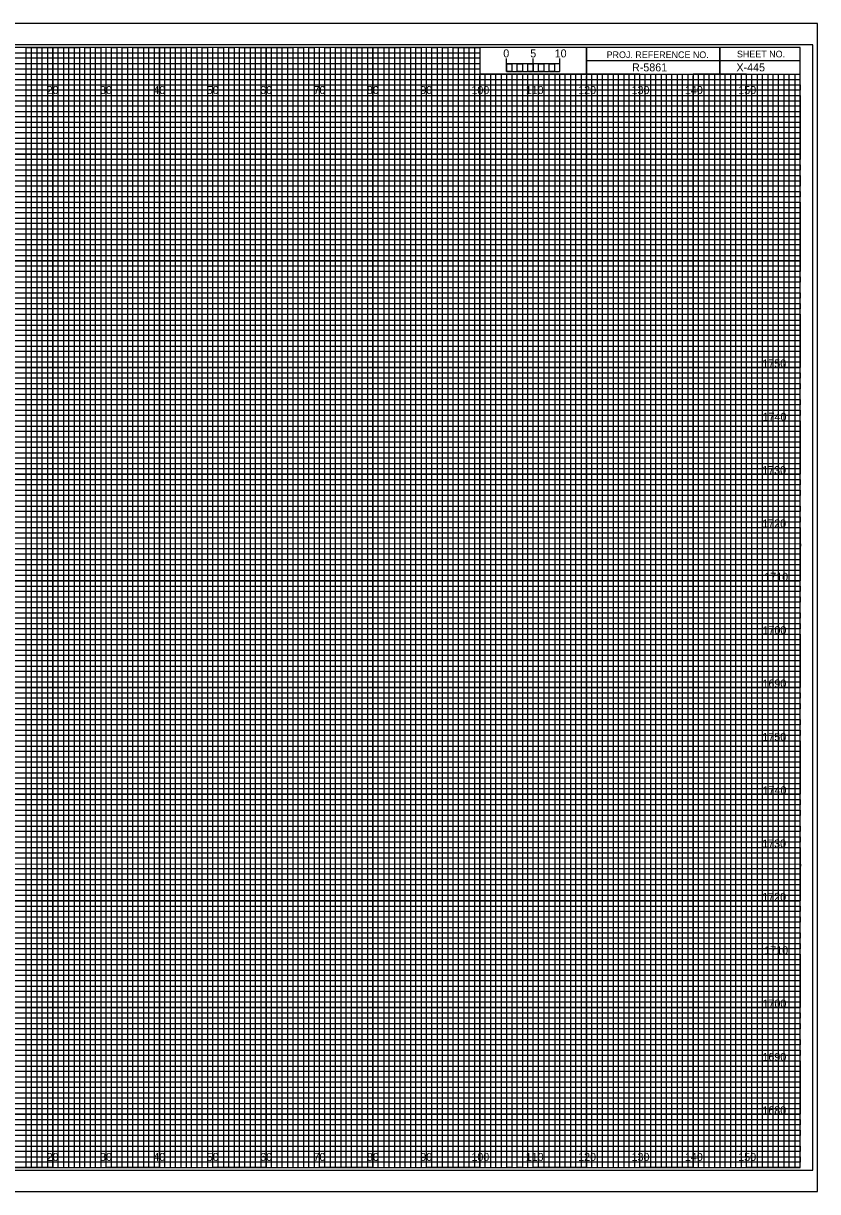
# Model space of a CAD drawing. Extents: x -13 to 323, y -5 to 1314.
# Drawn here: x 174.5 to 323.3, y 875.5 to 1094.5 of the extents above; entities that cross this region are included whole.
import ezdxf

# ---------------------------------------------------------------- set-up
doc = ezdxf.new("R2010")
doc.units = 0
for name, color, linetype in [('Prop XS Bar Scale Labels', 7, 'Continuous'), ('Prop XS Project Number', 7, 'Continuous'), ('Prop XS Sheet Number', 7, 'Continuous'), ('Raster_Level_0', 7, 'Continuous'), ('Scratch_Level_3', 7, 'Continuous'), ('Sheet Cross Section CELL', 7, 'Continuous'), ('Sheet Cross Section Grid Major CELL', 7, 'Continuous'), ('Sheet Cross Section Grid Middle CELL', 7, 'Continuous'), ('Sheet Cross Section Grid Minor 1 CELL', 7, 'Continuous'), ('Sheet Cross Section Grid Minor 2 CELL', 7, 'Continuous'), ('Sheet Cross Section Scale CELL', 7, 'Continuous'), ('Sheet Cutting Line CELL', 7, 'Continuous'), ('Sheet DOT Grid CELL', 7, 'Continuous'), ('Sheet Plot Border Inside CELL', 7, 'Continuous'), ('Sheet Plot Border Outside CELL', 7, 'Continuous')]:
    doc.layers.add(name, color=color, linetype=linetype)

msp = doc.modelspace()

# ---------------------------------------------------------------- linework, layer by layer
at = {"layer": 'Sheet Cross Section CELL'}
for p, q in [((305, 1090), (305, 1085)), ((305, 1085), (305, 1090)), ((280, 1087.5), (280, 1085)), ((320, 1087.49), (280, 1087.49)), ((280, 1085), (320, 1085))]:
    msp.add_line(p, q, dxfattribs=at)
for points in [[(320, 1090), (0, 1090), (0, 880), (320, 880)], [(280, 1090), (260, 1090), (260, 1085.03), (280, 1085.03)], [(320, 1090), (280, 1090), (280, 1085), (320, 1085)]]:
    msp.add_lwpolyline(points, close=True, dxfattribs=at)
at = {"layer": 'Sheet Cross Section Grid Major CELL'}
for p, q in [((190, 1090), (180, 1090)), ((180, 1090), (180, 880)), ((190, 880), (190, 1090)), ((210, 1090), (200, 1090)), ((200, 1090), (200, 880)), ((210, 880), (210, 1090)), ((230, 1090), (220, 1090)), ((220, 1090), (220, 880)), ((230, 880), (230, 1090)), ((250, 1090), (240, 1090)), ((240, 1090), (240, 880)), ((250, 880), (250, 1090)), ((260, 1090), (260, 880)), ((270, 880), (270, 1085)), ((290, 1085), (280, 1085)), ((280, 1085), (280, 880)), ((290, 880), (290, 1085)), ((310, 1085), (300, 1085)), ((300, 1085), (300, 880)), ((310, 880), (310, 1085)), ((180, 880), (170, 880)), ((200, 880), (190, 880)), ((220, 880), (210, 880)), ((240, 880), (230, 880)), ((260, 880), (250, 880)), ((280, 880), (270, 880)), ((300, 880), (290, 880)), ((320, 880), (310, 880)), ((320, 880), (320, 880))]:
    msp.add_line(p, q, dxfattribs=at)
for points in [[(0, 1080), (320, 1080), (320, 1070), (0, 1070)], [(0, 1060), (320, 1060), (320, 1050), (0, 1050)], [(0, 1040), (320, 1040), (320, 1030), (0, 1030)], [(0, 1020), (320, 1020), (320, 1010), (0, 1010)], [(0, 1000), (320, 1000), (320, 990), (0, 990)], [(0, 980), (320, 980), (320, 970), (0, 970)], [(0, 960), (320, 960), (320, 950), (0, 950)], [(0, 940), (320, 940), (320, 930), (0, 930)], [(0, 920), (320, 920), (320, 910), (0, 910)], [(0, 900), (320, 900), (320, 890), (0, 890)]]:
    msp.add_lwpolyline(points, dxfattribs=at)
at = {"layer": 'Sheet Cross Section Grid Middle CELL'}
for points in [[(165, 880), (175, 880), (175, 1090), (185, 1090), (185, 880), (195, 880), (195, 1090), (205, 1090), (205, 880), (215, 880), (215, 1090), (225, 1090), (225, 880), (235, 880), (235, 1090), (245, 1090), (245, 880), (255, 880), (255, 1090), (259.93, 1090), (260, 1090), (260, 1085), (264.99, 1085), (264.99, 880), (275, 880), (275, 1085), (285, 1085), (285, 880), (295, 880), (295, 1085), (305, 1085), (305, 880), (315, 880), (315, 1085)], [(0, 1085), (275, 1085)], [(0, 1065), (320, 1065), (320, 1075), (0, 1075)], [(0, 1045), (320, 1045), (320, 1055), (0, 1055)], [(0, 1025), (320, 1025), (320, 1035), (0, 1035)], [(0, 1005), (320, 1005), (320, 1015), (0, 1015)], [(0, 985), (320, 985), (320, 995), (0, 995)], [(0, 965), (320, 965), (320, 975), (0, 975)], [(0, 945), (320, 945), (320, 955), (0, 955)], [(0, 925), (320, 925), (320, 935), (0, 935)], [(0, 905), (320, 905), (320, 915), (0, 915)], [(0, 885), (320, 885), (320, 895), (0, 895)]]:
    msp.add_lwpolyline(points, dxfattribs=at)
at = {"layer": 'Sheet Cross Section Grid Minor 1 CELL'}
for p, q in [((0, 1089), (260, 1089)), ((260, 1089), (260, 1087.98)), ((260, 1087.98), (0, 1087.98)), ((0, 1087), (260, 1087)), ((260, 1087), (260, 1085.89)), ((260, 1085.89), (0, 1085.89)), ((0, 1084), (320, 1084))]:
    msp.add_line(p, q, dxfattribs=at)
for points in [[(0, 1083), (270, 1083), (320, 1083), (320, 1082), (0, 1082)], [(0, 1081), (320, 1081), (320, 1079), (0, 1079)], [(0, 1078), (320, 1078), (320, 1077), (0, 1076.98)], [(0, 1076), (320, 1076), (320, 1074), (0, 1074)], [(0, 1073), (320, 1073), (320, 1072), (0, 1072)], [(0, 1071), (320, 1071), (320, 1069), (0, 1069)], [(0, 1068), (320, 1068), (320, 1067), (0, 1067)], [(0, 1066), (320, 1066), (320, 1064), (0, 1064)], [(0, 1063), (320, 1063), (320, 1062), (0, 1062)], [(0, 1061), (320, 1061), (320, 1059), (0, 1059)], [(0, 1058), (320, 1058), (320, 1057), (0, 1057)], [(0, 1056), (320, 1056), (320, 1053.95), (320, 1053), (320, 1052), (0, 1052)], [(0, 1054), (320, 1054), (320, 1053), (0, 1053)], [(0, 1051), (320, 1051), (320, 1049), (0, 1049.03)], [(0, 1049.03), (320, 1049), (320, 1048), (0, 1048)], [(0, 1047), (320, 1047), (320, 1046), (0, 1046)], [(0, 1044), (320, 1044), (320, 1043), (0, 1043)], [(0, 1042), (320, 1042), (320, 1041), (0, 1041)], [(-0.07, 1038.89), (320, 1038.89), (320, 1037.88), (-0.07, 1037.88)], [(0, 1037), (320, 1037), (320, 1036), (0, 1036)], [(0, 1034), (320, 1034), (320, 1033), (0, 1033)], [(0, 1032), (320, 1032), (320, 1031), (0, 1031)], [(0, 1029), (320, 1029), (320, 1028), (0, 1028)], [(0, 1027), (320, 1027), (320, 1026), (0, 1026)], [(0, 1024), (320, 1024), (320, 1023), (0, 1023)], [(0, 1022), (320, 1022), (320, 1021), (0, 1021)], [(0, 1019), (320, 1019), (319.99, 1017.98), (0, 1018)], [(0, 1017), (320, 1017), (320, 1016), (0, 1016)], [(0, 1014), (320, 1014), (320, 1013), (0, 1013)], [(0, 1012), (320, 1012), (320, 1011), (0, 1011)], [(0, 1009), (320, 1009), (320, 1008), (0, 1008)], [(0, 1007), (320, 1007), (320, 1006), (0, 1006)], [(0, 1004), (320, 1004), (320, 1003), (0, 1003)], [(0, 1002), (320, 1002), (320, 1001), (0, 1001)], [(0, 999), (320, 999), (320, 998), (0, 998)], [(0, 996.99), (320.07, 996.91), (320, 996), (0, 996)], [(0, 994), (320, 994), (320, 993), (0, 993)], [(0, 992), (320, 992), (320, 991), (0, 991)], [(0, 989), (320, 989), (320, 988), (0, 988)], [(0, 987), (320, 987), (320, 986), (0, 986)], [(0, 984), (320, 984), (320, 983), (0, 983)], [(0, 982), (320, 982), (320, 981), (0, 981)], [(0, 979), (320, 979), (320, 978), (0, 978)], [(0, 977), (320, 977), (320, 976), (0, 976)], [(0, 974), (320, 974), (320, 973), (0, 973)], [(0, 972), (320, 972), (320, 971), (0, 971)], [(0, 969), (320, 969), (320, 968), (0, 968)], [(0, 967), (320, 967), (320, 966), (0, 966)], [(0, 964), (320, 964), (320, 963), (0, 963)], [(0, 962), (320, 962), (320, 961), (0, 961)], [(0, 959), (320, 959), (319.99, 957.98), (0, 958)], [(0, 957), (320, 957), (320, 956), (0, 956)], [(0, 954), (320, 954), (320, 953), (0, 953)], [(0, 952), (320, 952), (320, 951), (0, 951)], [(0, 949), (320, 949), (320, 948), (0, 948)], [(0, 947), (320, 947), (320, 946), (0, 946)], [(0, 944), (320, 944), (320, 943), (0, 943)], [(0, 942), (320, 942), (320, 941), (0, 941)], [(0, 939), (320, 939), (320, 938), (0, 938)], [(0, 936.99), (320.07, 936.91), (320, 936), (0, 936)], [(0, 934), (320, 934), (320, 933), (0, 933)], [(0, 932), (320, 932), (320, 931), (0, 931)], [(0, 929), (320, 929), (320, 928), (0, 928)], [(0, 927), (320, 927), (320, 926), (0, 926)], [(0, 924), (320, 924), (320, 923), (0, 923)], [(0, 922), (320, 922), (320, 921), (0, 921)], [(0, 919), (320, 919), (320, 918), (0, 918)], [(0, 917), (320, 917), (320, 916), (0, 916)], [(0, 914), (320, 914), (320, 913), (0, 913)], [(0, 912), (320, 912), (320, 911), (0, 911)], [(0, 909), (320, 909), (320, 908), (0, 908)], [(0, 907), (320, 907), (320, 906), (0, 906)], [(0, 904), (320, 904), (320, 903), (0, 903)], [(0, 902), (320, 902), (320, 901), (0, 901)], [(0, 899), (320, 899), (320, 898), (0, 898)], [(0, 897), (320, 897), (320, 896), (0, 896)], [(0, 894), (320, 894), (320, 893), (0, 893)], [(0, 892), (320, 892), (320, 891), (0, 891)], [(0, 889), (320, 889), (320, 888), (0, 888)], [(0, 887), (320, 887), (320, 886), (0, 886)], [(0, 884), (320, 884), (320, 883), (0, 883)], [(0, 882), (320, 882), (320, 881), (0, 881)]]:
    msp.add_lwpolyline(points, dxfattribs=at)
at = {"layer": 'Sheet Cross Section Grid Minor 2 CELL'}
for p, q in [((267, 1085), (266.01, 1085)), ((266.01, 1085), (266.01, 880)), ((267, 880), (267, 1085)), ((269, 1085), (268, 1085)), ((268, 1085), (268, 880)), ((269, 880), (269, 1085)), ((266.01, 880), (265, 880)), ((268, 880), (267, 880))]:
    msp.add_line(p, q, dxfattribs=at)
for points in [[(175, 880), (176, 880), (176, 1090), (177, 1090), (177, 880)], [(177, 880), (178, 880), (178, 1090), (179, 1090), (179, 880)], [(180, 880), (181, 880), (181, 1090), (182, 1090), (182, 880)], [(182, 880), (183, 880), (183, 1090), (184, 1090), (184, 880)], [(185, 880), (186, 880), (186, 1090), (187, 1090), (187, 880)], [(187, 880), (188, 880), (188, 1090), (189, 1090), (189, 880)], [(190, 880), (191, 880), (191, 1090), (192, 1090), (192, 880)], [(192, 880), (193, 880), (193, 1090), (194, 1090), (194, 880)], [(195, 880), (196, 880), (196, 1090), (197, 1090), (197, 880)], [(197, 880), (198, 880), (198, 1090), (199, 1090), (199, 880)], [(200, 880), (201, 880), (201, 1090), (202, 1090), (202, 880)], [(202, 880), (203, 880), (203, 1090), (204, 1090), (204, 880)], [(205, 880), (206, 880), (206, 1090), (207, 1090), (207, 880)], [(207, 880), (208, 880), (208, 1090), (209, 1090), (209, 880)], [(210, 880), (211, 880), (211, 1090), (212, 1090), (212, 880)], [(212, 880), (213, 880), (213, 1090), (214, 1090), (214, 880)], [(215, 880), (216, 880), (216, 1090), (217, 1090), (217, 880)], [(217, 880), (218, 880), (218, 1090), (219, 1090), (219, 880)], [(220, 880), (221, 880), (221, 1090), (222, 1090), (222, 880)], [(222, 880), (223, 880), (223, 1090), (224, 1090), (224, 880)], [(225, 880), (226, 880), (226, 1090), (227, 1090), (227, 880)], [(227, 880), (228, 880), (228, 1090), (229, 1090), (229, 880)], [(230, 880), (231, 880), (231, 1090), (232, 1090), (232, 880)], [(232, 880), (233, 880), (233, 1090), (234, 1090), (234, 880)], [(235, 880), (236, 880), (236, 1090), (237, 1090), (237, 880)], [(237, 880), (238, 880), (238, 1090), (239, 1090), (239, 880)], [(240, 880), (241, 880), (241, 1090), (242, 1090), (242, 880)], [(242, 880), (243, 880), (243, 1090), (244, 1090), (244, 880)], [(245, 880), (246, 880), (246, 1090), (247, 1090), (247, 880)], [(247, 880), (248, 880), (248, 1090), (249, 1090), (249, 880)], [(250, 880), (251, 880), (251, 1090), (252, 1090), (252, 880)], [(252, 880), (253, 880), (253, 1090), (254, 1090), (254, 880)], [(255, 880), (256, 880), (256, 1090), (257, 1090), (257, 880)], [(257, 880), (258, 880), (258, 1090), (259, 1090), (259, 880)], [(260, 880), (261, 880), (261, 1085), (262.02, 1085), (262.02, 880)], [(262, 880), (263, 880), (263, 1085), (263.99, 1085), (263.99, 880)], [(270, 880), (270.98, 880), (270.98, 1085), (272, 1085), (272, 880)], [(272, 880), (273, 880), (273, 1085), (274.05, 1085), (274.05, 880)], [(275, 880), (276, 880), (276, 1085), (277, 1085), (277, 880)], [(277, 880), (278, 880), (278, 1085), (279, 1085), (279, 880)], [(280, 880), (281, 880), (281, 1085), (282, 1085), (282, 880)], [(282, 880), (283, 880), (283, 1085), (284, 1085), (284, 880)], [(285, 880), (286, 880), (286, 1085), (287, 1085), (287, 880)], [(287, 880), (288, 880), (288, 1085), (289, 1085), (289, 880)], [(290, 880), (291, 880), (291, 1085), (292, 1085), (292, 880)], [(292, 880), (293, 880), (293, 1085), (294, 1085), (294, 880)], [(295, 880), (296, 880), (296, 1085), (297, 1085), (297, 880)], [(297, 880), (298, 880), (298, 1085), (299, 1085), (299, 880)], [(300, 880), (301, 880), (301, 1085), (302, 1085), (302, 880)], [(302, 880), (303, 880), (303, 1085), (304, 1085), (304, 880)], [(305, 880), (306, 880), (306, 1085), (307, 1085), (307, 880)], [(307, 880), (308, 880), (308, 1085), (309, 1085), (309, 880)], [(310, 880), (311, 880), (311, 1085), (312, 1085), (312, 880)], [(312, 880), (313, 880), (313, 1085), (314, 1085), (314, 880)], [(315, 880), (316, 880), (316, 1085), (317, 1085), (317, 880)], [(317, 880), (318, 880), (318, 1085), (319, 1085), (319, 880)]]:
    msp.add_lwpolyline(points, dxfattribs=at)
at = {"layer": 'Sheet Cross Section Scale CELL'}
for p, q in [((265, 1085.49), (265, 1087.9)), ((265, 1086.9), (265, 1087.9)), ((270, 1085.49), (270, 1087.9)), ((275, 1085.49), (275, 1087.9)), ((275, 1086.9), (275, 1087.9))]:
    msp.add_line(p, q, dxfattribs=at)
for points in [[(275, 1086.9), (265, 1086.9), (265, 1085.49), (275, 1085.49)], [(265, 1086.9), (266, 1086.9), (266, 1085.49), (265, 1085.49)], [(267, 1086.9), (268, 1086.9), (268, 1085.49), (267, 1085.49)], [(269, 1086.9), (270, 1086.9), (270, 1085.49), (269, 1085.49)], [(271, 1086.9), (272, 1086.9), (272, 1085.49), (271, 1085.49)], [(273, 1086.9), (274, 1086.9), (274, 1085.49), (273, 1085.49)]]:
    msp.add_lwpolyline(points, close=True, dxfattribs=at)
at = {"layer": 'Sheet Cutting Line CELL'}
for p, q in [((323.3, 1094.5), (-13.4, 1094.5)), ((-13.4, 875.5), (323.3, 875.5))]:
    msp.add_line(p, q, dxfattribs=at)
at = {"layer": 'Sheet DOT Grid CELL'}
for p, q in [((180, 880), (180, 1090)), ((190, 880), (190, 1090)), ((200, 880), (200, 1090)), ((210, 880), (210, 1090)), ((220, 880), (220, 1090)), ((230, 880), (230, 1090)), ((240, 880), (240, 1090)), ((250, 880), (250, 1090)), ((260, 880), (260, 1084.69)), ((270, 880), (270, 1084.69)), ((280, 880), (280, 1084.69)), ((290, 880), (290, 1084.69)), ((300, 880), (300, 1084.69)), ((310, 880), (310, 1084.69)), ((0, 1080), (320, 1080)), ((0, 1070), (320, 1070)), ((0, 1060), (320, 1060)), ((0, 1050), (320, 1050)), ((0, 1040), (320, 1040)), ((0, 1030), (320, 1030)), ((0, 1020), (320, 1020)), ((0, 1010), (320, 1010)), ((0, 1000), (320, 1000)), ((0, 990), (320, 990)), ((0, 980), (320, 980)), ((0, 970), (320, 970)), ((0, 960), (320, 960)), ((0, 950), (320, 950)), ((0, 940), (320, 940)), ((0, 930), (320, 930)), ((0, 920), (320, 920)), ((0, 910), (320, 910)), ((0, 900), (320, 900)), ((0, 890), (320, 890))]:
    msp.add_line(p, q, dxfattribs=at)
at = {"layer": 'Sheet Plot Border Inside CELL'}
msp.add_lwpolyline([(-10.8, 879.5), (322.4, 879.5), (322.4, 1090.5), (-10.8, 1090.5)], close=True, dxfattribs=at)
at = {"layer": 'Sheet Plot Border Outside CELL'}
msp.add_lwpolyline([(-13.4, 875.5), (323.3, 875.5), (323.3, 1094.5), (-13.4, 1094.5)], close=True, dxfattribs=at)

# ---------------------------------------------------------------- texts
at = {"layer": 'Prop XS Bar Scale Labels'}
for s, p in [('5', (269.47, 1088.12)), ('10', (274.04, 1088.12))]:
    msp.add_text(s, height=1.5, dxfattribs=at).set_placement(p)
at = {"layer": 'Prop XS Project Number'}
msp.add_text('R-5861', height=1.5, dxfattribs=at).set_placement((288.53, 1085.5))
at = {"layer": 'Prop XS Sheet Number'}
msp.add_text('X-445', height=1.5, dxfattribs=at).set_placement((308.09, 1085.5))
at = {"layer": 'Raster_Level_0'}
for s, p in [('20', (178.86, 1081.25)), ('30', (188.86, 1081.25)), ('40', (198.86, 1081.25)), ('50', (208.86, 1081.25)), ('60', (218.86, 1081.25)), ('70', (228.86, 1081.25)), ('80', (238.86, 1081.25)), ('90', (248.86, 1081.25)), ('100', (258.44, 1081.25)), ('110', (268.62, 1081.25)), ('120', (278.44, 1081.25)), ('130', (288.44, 1081.25)), ('140', (298.44, 1081.25)), ('150', (308.44, 1081.25)), ('20', (178.86, 881.25)), ('30', (188.86, 881.25)), ('40', (198.86, 881.25)), ('50', (208.86, 881.25)), ('60', (218.86, 881.25)), ('70', (228.86, 881.25)), ('80', (238.86, 881.25)), ('90', (248.86, 881.25)), ('100', (258.44, 881.25)), ('110', (268.62, 881.25)), ('120', (278.44, 881.25)), ('130', (288.44, 881.25)), ('140', (298.44, 881.25)), ('150', (308.44, 881.25))]:
    msp.add_text(s, height=1.5, dxfattribs=at).set_placement(p)
at = {"layer": 'Scratch_Level_3'}
for s, p in [('1750', (312.96, 1030)), ('1740', (313, 1020)), ('1730', (312.92, 1010)), ('1720', (312.93, 1000)), ('1710', (313.31, 990)), ('1700', (312.98, 980)), ('1690', (312.97, 970)), ('1750', (312.96, 960)), ('1740', (313, 950)), ('1730', (312.92, 940)), ('1720', (312.93, 930)), ('1710', (313.31, 920)), ('1700', (312.98, 910)), ('1690', (312.97, 900)), ('1680', (312.95, 890))]:
    msp.add_text(s, height=1.5, dxfattribs=at).set_placement(p)
at = {"layer": 'Sheet Cross Section CELL'}
for s, p in [('PROJ. REFERENCE NO.', (283.77, 1087.99)), ('SHEET NO.', (308.19, 1088.12))]:
    msp.add_text(s, height=1.25, dxfattribs=at).set_placement(p)
at = {"layer": 'Sheet Cross Section Scale CELL'}
msp.add_text('0', height=1.5, dxfattribs=at).set_placement((264.41, 1088.12))

doc.saveas('drawing.dxf')
